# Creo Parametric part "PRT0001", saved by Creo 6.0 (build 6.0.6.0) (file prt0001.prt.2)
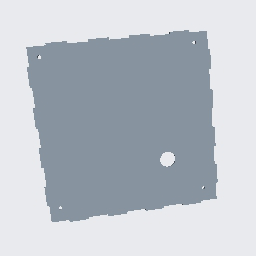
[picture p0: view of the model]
Units: Inch lbm Second (Pro/E Default); INCH, POUND, SECS

Created from: INLBS_PART_SOLID.PRT

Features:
  1. datum plane "RIGHT"
  2. datum plane "TOP"
  3. datum plane "FRONT"
  4. coordinate system
  5. sketch "Sketch 1"
  6. extrusion "Extrude 1"
  7. sketch "Sketch 2"
  8. extruded cut "Extrude 2"
  9. sketch "Sketch 3"
  10. extruded cut "Extrude 3"
  11. sketch "Sketch 4"
  12. extruded cut "Extrude 4"

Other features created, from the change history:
  extrusion "Extrude 2" (2 times)
  mirror "Mirror 1"

Surfaces: 70 plane, 5 cylinder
